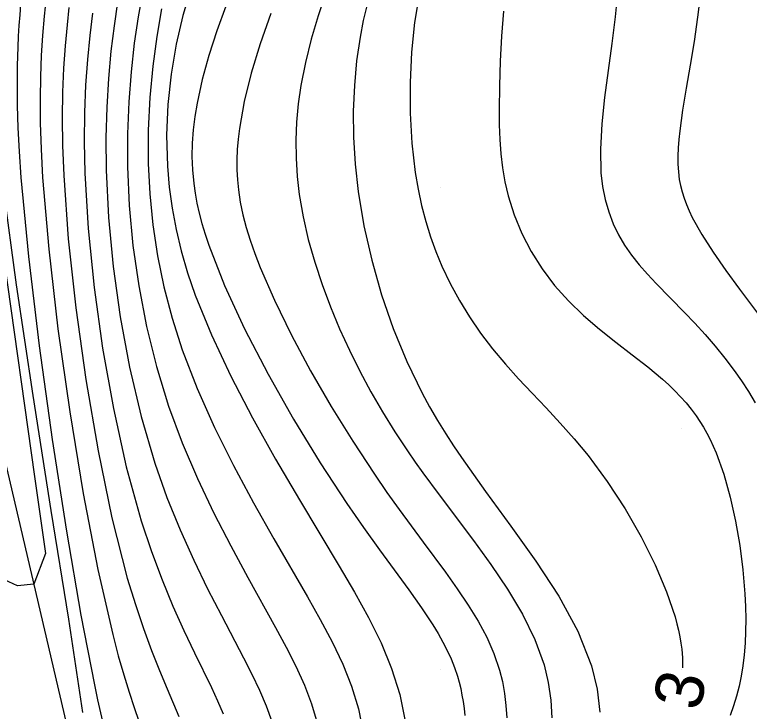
# Model space of a CAD drawing. Extents: x 2602990 to 2605851, y 618069 to 619180.
# Drawn here: x 2603422.33 to 2603452.82, y 618688.28 to 618717.18 of the extents above; entities that cross this region are included whole.
import ezdxf

# ---------------------------------------------------------------- set-up
doc = ezdxf.new("R2010")
doc.units = 0
for name, color, linetype in [('DTM Contours Major', 7, 'Continuous'), ('DTM Contours Minor', 7, 'Continuous'), ('DTM Contours Minor Text', 7, 'Continuous'), ('Exist DTM QL2 LIDAR Elevation Point', 7, 'Continuous'), ('Exist Roads EOP', 7, 'Continuous'), ('PH Exist DTM Breakline', 7, 'Continuous')]:
    doc.layers.add(name, color=color, linetype=linetype)

msp = doc.modelspace()

# ---------------------------------------------------------------- linework, layer by layer
at = {"layer": 'DTM Contours Major'}
msp.add_lwpolyline([(2603428.429, 618717.431), (2603428.227, 618716.285), (2603428.061, 618715.052), (2603427.942, 618713.751), (2603427.877, 618712.399), (2603427.877, 618711.015), (2603427.94, 618709.745), (2603428.067, 618708.467), (2603428.261, 618707.18), (2603428.526, 618705.886), (2603428.864, 618704.587), (2603429.28, 618703.285), (2603429.901, 618701.668), (2603430.619, 618700.061), (2603431.406, 618698.478), (2603432.236, 618696.931), (2603433.079, 618695.435), (2603434.479, 618693.028), (2603435.015, 618692.083), (2603435.507, 618691.156), (2603435.942, 618690.238), (2603436.31, 618689.319), (2603436.598, 618688.387), (2603436.825, 618687.25)], dxfattribs=at)
at = {"layer": 'DTM Contours Minor'}
for points in [[(2603427.636, 618718.105), (2603427.457, 618717.098), (2603427.296, 618715.999), (2603427.164, 618714.819), (2603427.067, 618713.565), (2603427.015, 618712.247), (2603427.015, 618710.875), (2603427.088, 618709.261), (2603427.241, 618707.606), (2603427.478, 618705.928), (2603427.801, 618704.247), (2603428.212, 618702.58), (2603428.713, 618700.945), (2603429.281, 618699.413), (2603429.914, 618697.933), (2603430.593, 618696.507), (2603431.296, 618695.14), (2603432.002, 618693.836), (2603433.158, 618691.758), (2603433.597, 618690.946), (2603433.999, 618690.152), (2603434.355, 618689.369), (2603434.654, 618688.587), (2603434.889, 618687.798)], [(2603429.658, 618718.313), (2603429.312, 618717.157), (2603429.032, 618715.955), (2603428.823, 618714.717), (2603428.69, 618713.456), (2603428.638, 618712.18), (2603428.671, 618710.902), (2603428.745, 618710.029), (2603428.864, 618709.155), (2603429.03, 618708.275), (2603429.244, 618707.385), (2603429.509, 618706.479), (2603429.826, 618705.553), (2603430.498, 618703.894), (2603431.301, 618702.188), (2603432.199, 618700.46), (2603433.158, 618698.738), (2603434.145, 618697.048), (2603435.796, 618694.308), (2603436.432, 618693.229), (2603437.016, 618692.17), (2603437.535, 618691.117), (2603437.973, 618690.06), (2603438.315, 618688.984), (2603438.583, 618687.665)], [(2603435.258, 618718.13), (2603434.921, 618717.139), (2603434.632, 618716.163), (2603434.393, 618715.2), (2603434.209, 618714.252), (2603434.101, 618713.487), (2603434.032, 618712.729), (2603434.001, 618711.976), (2603434.01, 618711.226), (2603434.057, 618710.476), (2603434.143, 618709.725), (2603434.302, 618708.791), (2603434.516, 618707.855), (2603434.78, 618706.919), (2603435.087, 618705.988), (2603435.434, 618705.064), (2603435.816, 618704.152), (2603436.222, 618703.264), (2603436.656, 618702.392), (2603437.115, 618701.537), (2603437.598, 618700.699), (2603438.104, 618699.882), (2603438.629, 618699.084), (2603438.948, 618698.624), (2603439.273, 618698.169), (2603439.943, 618697.263), (2603441.369, 618695.374), (2603442.095, 618694.375), (2603442.782, 618693.352), (2603443.4, 618692.313), (2603443.917, 618691.262), (2603444.3, 618690.206), (2603444.473, 618689.477), (2603444.578, 618688.747), (2603444.624, 618688.015)], [(2603439.111, 618718.024), (2603438.925, 618716.859), (2603438.801, 618715.634), (2603438.74, 618714.374), (2603438.745, 618713.105), (2603438.816, 618711.852), (2603438.957, 618710.641), (2603439.075, 618709.941), (2603439.219, 618709.264), (2603439.389, 618708.607), (2603439.586, 618707.971), (2603439.809, 618707.352), (2603440.058, 618706.749), (2603440.401, 618706.027), (2603440.784, 618705.326), (2603441.206, 618704.642), (2603441.665, 618703.975), (2603442.162, 618703.322), (2603442.695, 618702.682), (2603443.236, 618702.08), (2603443.801, 618701.478), (2603444.381, 618700.868), (2603444.967, 618700.24), (2603445.551, 618699.585), (2603446.124, 618698.894), (2603446.921, 618697.818), (2603447.66, 618696.68), (2603448.328, 618695.515), (2603448.906, 618694.357), (2603449.381, 618693.241), (2603449.735, 618692.2), (2603449.814, 618691.916), (2603449.881, 618691.64), (2603449.936, 618691.372), (2603449.98, 618691.11), (2603450.012, 618690.854), (2603450.038, 618690.505), (2603450.042, 618690.214), (2603450.037, 618690.082)], [(2603450.787, 618718.082), (2603450.672, 618717.076), (2603450.524, 618716.072), (2603450.359, 618715.085), (2603450.194, 618714.129), (2603450.045, 618713.219), (2603449.928, 618712.369), (2603449.89, 618712.004), (2603449.863, 618711.653), (2603449.851, 618711.315), (2603449.853, 618710.986), (2603449.873, 618710.666), (2603449.912, 618710.352), (2603449.961, 618710.091), (2603450.026, 618709.832), (2603450.106, 618709.573), (2603450.204, 618709.308), (2603450.319, 618709.041), (2603450.449, 618708.768), (2603450.84, 618708.066), (2603451.31, 618707.331), (2603451.841, 618706.571), (2603452.414, 618705.79), (2603453.606, 618704.195)], [(2603423.632, 618717.912), (2603423.549, 618717.125), (2603423.482, 618716.318), (2603423.432, 618715.493), (2603423.398, 618714.621), (2603423.384, 618713.691), (2603423.392, 618712.691), (2603423.427, 618711.609), (2603423.49, 618710.435), (2603423.743, 618707.461), (2603424.127, 618704.155), (2603424.614, 618700.709), (2603425.175, 618697.316), (2603425.779, 618694.17), (2603426.399, 618691.462), (2603426.632, 618690.586), (2603426.86, 618689.795), (2603427.081, 618689.079), (2603427.293, 618688.433), (2603427.904, 618686.649)], [(2603422.576, 618717.611), (2603422.539, 618717.173), (2603422.507, 618716.733), (2603422.481, 618716.288), (2603422.461, 618715.834), (2603422.438, 618715.071), (2603422.431, 618714.268), (2603422.44, 618713.413), (2603422.468, 618712.496), (2603422.518, 618711.505), (2603422.591, 618710.429), (2603422.9, 618707.147), (2603423.347, 618703.438), (2603423.887, 618699.555), (2603424.477, 618695.749), (2603425.075, 618692.272), (2603425.637, 618689.377), (2603425.769, 618688.763), (2603426.016, 618687.678)], [(2603424.585, 618717.478), (2603424.505, 618716.766), (2603424.424, 618715.891), (2603424.361, 618714.962), (2603424.32, 618713.97), (2603424.304, 618712.905), (2603424.318, 618711.756), (2603424.365, 618710.514), (2603424.556, 618707.888), (2603424.868, 618705.02), (2603425.284, 618702.044), (2603425.79, 618699.094), (2603426.369, 618696.305), (2603427.006, 618693.808), (2603427.339, 618692.711), (2603427.676, 618691.711), (2603428.012, 618690.801), (2603428.34, 618689.973), (2603428.655, 618689.217), (2603429.145, 618688.07)], [(2603426.604, 618717.697), (2603426.456, 618716.718), (2603426.327, 618715.666), (2603426.223, 618714.54), (2603426.152, 618713.342), (2603426.119, 618712.071), (2603426.131, 618710.728), (2603426.23, 618708.776), (2603426.425, 618706.733), (2603426.715, 618704.645), (2603427.099, 618702.558), (2603427.577, 618700.519), (2603428.147, 618698.573), (2603428.65, 618697.154), (2603429.192, 618695.816), (2603429.759, 618694.555), (2603430.336, 618693.368), (2603430.908, 618692.252), (2603431.83, 618690.498), (2603432.177, 618689.818), (2603432.492, 618689.156), (2603432.771, 618688.506), (2603433.007, 618687.86)], [(2603431.089, 618717.535), (2603430.715, 618716.51), (2603430.387, 618715.492), (2603430.113, 618714.492), (2603429.9, 618713.517), (2603429.805, 618712.957), (2603429.736, 618712.403), (2603429.695, 618711.853), (2603429.683, 618711.301), (2603429.705, 618710.743), (2603429.76, 618710.175), (2603429.819, 618709.777), (2603429.896, 618709.37), (2603429.991, 618708.954), (2603430.104, 618708.525), (2603430.236, 618708.083), (2603430.386, 618707.626), (2603431.04, 618705.95), (2603431.874, 618704.145), (2603432.844, 618702.273), (2603433.905, 618700.399), (2603435.01, 618698.588), (2603436.116, 618696.903), (2603436.809, 618695.908), (2603437.474, 618694.985), (2603438.688, 618693.325), (2603439.219, 618692.573), (2603439.687, 618691.863), (2603439.905, 618691.505), (2603440.104, 618691.153), (2603440.283, 618690.803), (2603440.443, 618690.453), (2603440.583, 618690.099), (2603440.704, 618689.738), (2603440.775, 618689.483), (2603440.839, 618689.223), (2603440.893, 618688.955), (2603440.94, 618688.681), (2603440.979, 618688.398), (2603441.011, 618688.106)], [(2603436.953, 618717.607), (2603436.797, 618716.939), (2603436.664, 618716.254), (2603436.52, 618715.268), (2603436.426, 618714.244), (2603436.384, 618713.187), (2603436.395, 618712.1), (2603436.461, 618710.988), (2603436.586, 618709.854), (2603436.822, 618708.43), (2603437.146, 618706.996), (2603437.554, 618705.567), (2603438.042, 618704.16), (2603438.605, 618702.791), (2603439.241, 618701.476), (2603439.55, 618700.907), (2603439.874, 618700.347), (2603440.216, 618699.791), (2603440.534, 618699.301), (2603440.867, 618698.808), (2603441.868, 618697.404), (2603442.921, 618695.968), (2603443.957, 618694.514), (2603444.905, 618693.054), (2603445.698, 618691.602), (2603446.267, 618690.17), (2603446.499, 618689.202), (2603446.612, 618688.249)], [(2603447.299, 618717.647), (2603447.246, 618717.089), (2603447.113, 618715.989), (2603446.959, 618714.871), (2603446.811, 618713.755), (2603446.694, 618712.661), (2603446.635, 618711.61), (2603446.66, 618710.621), (2603446.728, 618710.051), (2603446.835, 618709.51), (2603446.982, 618708.998), (2603447.166, 618708.513), (2603447.385, 618708.054), (2603447.64, 618707.619), (2603447.93, 618707.201), (2603448.248, 618706.801), (2603448.589, 618706.413), (2603448.948, 618706.034), (2603450.127, 618704.833), (2603450.558, 618704.378), (2603450.982, 618703.911), (2603451.397, 618703.43), (2603451.799, 618702.936), (2603452.186, 618702.426), (2603452.491, 618701.992), (2603452.782, 618701.545), (2603453.057, 618701.085)], [(2603425.561, 618717.254), (2603425.444, 618716.317), (2603425.347, 618715.321), (2603425.273, 618714.258), (2603425.228, 618713.123), (2603425.217, 618711.907), (2603425.246, 618710.607), (2603425.384, 618708.317), (2603425.631, 618705.87), (2603425.982, 618703.348), (2603426.428, 618700.838), (2603426.964, 618698.423), (2603427.581, 618696.188), (2603428.005, 618694.912), (2603428.449, 618693.733), (2603428.901, 618692.644), (2603429.353, 618691.636), (2603429.794, 618690.704), (2603430.492, 618689.262), (2603430.751, 618688.709), (2603430.987, 618688.175)], [(2603432.958, 618717.236), (2603432.516, 618715.979), (2603432.145, 618714.755), (2603431.855, 618713.578), (2603431.657, 618712.462), (2603431.604, 618712.018), (2603431.569, 618711.585), (2603431.552, 618711.161), (2603431.554, 618710.742), (2603431.575, 618710.327), (2603431.616, 618709.914), (2603431.692, 618709.402), (2603431.799, 618708.886), (2603431.935, 618708.361), (2603432.099, 618707.824), (2603432.292, 618707.271), (2603432.514, 618706.699), (2603433.108, 618705.335), (2603433.817, 618703.892), (2603434.613, 618702.409), (2603435.469, 618700.927), (2603436.36, 618699.483), (2603437.257, 618698.118), (2603437.779, 618697.365), (2603438.292, 618696.648), (2603439.28, 618695.304), (2603440.204, 618694.05), (2603440.693, 618693.363), (2603441.147, 618692.688), (2603441.558, 618692.018), (2603441.918, 618691.35), (2603442.219, 618690.676), (2603442.452, 618689.993), (2603442.571, 618689.512), (2603442.658, 618689.023), (2603442.716, 618688.523), (2603442.75, 618688.009)], [(2603442.609, 618717.324), (2603442.534, 618716.287), (2603442.478, 618715.255), (2603442.443, 618714.237), (2603442.433, 618713.242), (2603442.44, 618712.62), (2603442.464, 618712.01), (2603442.507, 618711.412), (2603442.575, 618710.824), (2603442.673, 618710.245), (2603442.804, 618709.673), (2603443.054, 618708.88), (2603443.376, 618708.107), (2603443.766, 618707.357), (2603444.221, 618706.638), (2603444.737, 618705.954), (2603445.308, 618705.311), (2603445.937, 618704.704), (2603446.6, 618704.136), (2603447.278, 618703.597), (2603447.952, 618703.077), (2603448.603, 618702.568), (2603449.211, 618702.061), (2603449.475, 618701.821), (2603449.727, 618701.578), (2603449.966, 618701.331), (2603450.192, 618701.076), (2603450.405, 618700.814), (2603450.606, 618700.541), (2603450.763, 618700.308), (2603450.913, 618700.065), (2603451.055, 618699.814), (2603451.189, 618699.554), (2603451.317, 618699.283), (2603451.439, 618699.001), (2603451.757, 618698.122), (2603452.025, 618697.172), (2603452.245, 618696.176), (2603452.417, 618695.159), (2603452.543, 618694.146), (2603452.626, 618693.16), (2603452.653, 618692.622), (2603452.666, 618692.1), (2603452.663, 618691.594), (2603452.643, 618691.103), (2603452.606, 618690.627), (2603452.549, 618690.164), (2603452.477, 618689.736), (2603452.388, 618689.318), (2603452.281, 618688.909), (2603452.159, 618688.508), (2603452.021, 618688.111)], [(2603421.854, 618709.99), (2603422.387, 618705.974), (2603423.08, 618701.378), (2603423.836, 618696.615), (2603424.559, 618692.097), (2603425.152, 618688.236)], [(2603421.9, 618706.959), (2603423.158, 618698.028), (2603423.611, 618694.822), (2603423.127, 618693.556), (2603422.45, 618693.487), (2603421.539, 618693.901)]]:
    msp.add_lwpolyline(points, dxfattribs=at)
at = {"layer": 'Exist DTM QL2 LIDAR Elevation Point'}
for p, q in [((2603430, 618710), (2603430, 618710)), ((2603440, 618710), (2603440, 618710)), ((2603450, 618710), (2603450, 618710)), ((2603440, 618700), (2603440, 618700)), ((2603450, 618700), (2603450, 618700)), ((2603440, 618690), (2603440, 618690)), ((2603450, 618690), (2603450, 618690))]:
    msp.add_line(p, q, dxfattribs=at)
at = {"layer": 'Exist Roads EOP'}
msp.add_spline([(2603230.17, 618389.98), (2603282.929, 618409.597), (2603332.773, 618427.868), (2603388.167, 618448.413), (2603437.203, 618466.721), (2603490.778, 618486.527), (2603539.039, 618504.558), (2603597.451, 618526.156), (2603651.053, 618545.972), (2603705.208, 618566.084), (2603762.02, 618587.183), (2603820.334, 618609.162), (2603876.341, 618629.99), (2603934.909, 618652.28), (2603996.409, 618675.568), (2604033.216, 618689.957), (2604052.01, 618697.199)], degree=3, dxfattribs=at)
at = {"layer": 'PH Exist DTM Breakline'}
msp.add_lwpolyline([(2603420.106, 618512.049), (2603420.211, 618516.533), (2603420.648, 618529.041), (2603420.819, 618538.47), (2603422.128, 618549.088), (2603423.344, 618553.609), (2603424.552, 618556.495), (2603427.152, 618561.197), (2603431.339, 618569.035), (2603433.508, 618575.626), (2603437.546, 618591.762), (2603439.238, 618603.824), (2603439.585, 618610.612), (2603438.591, 618626.145), (2603435.827, 618639.611), (2603430.526, 618661.513), (2603425.292, 618684.296), (2603417.979, 618715.577)], dxfattribs=at)

# ---------------------------------------------------------------- texts
at = {"layer": 'DTM Contours Minor Text'}
msp.add_text('3', height=2, rotation=78.8362, dxfattribs=at).set_placement((2603450.765, 618688.256))

doc.saveas('drawing.dxf')
